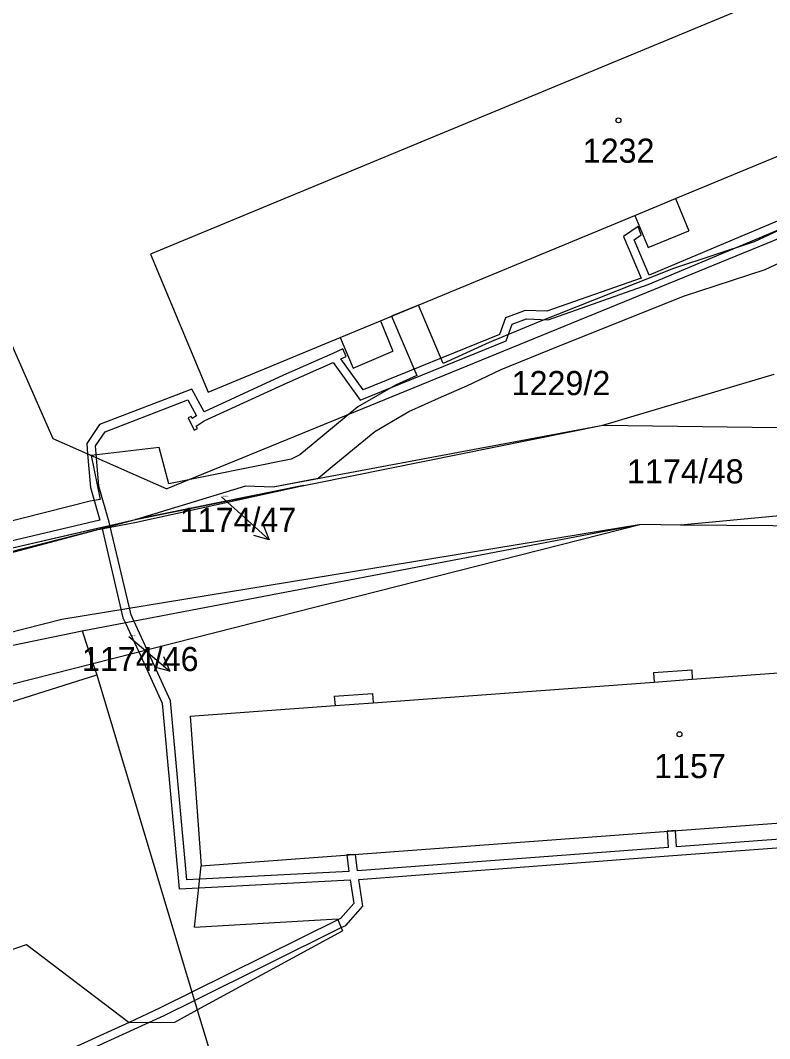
# Model space of a CAD drawing. Extents: x -785744 to -782822, y -1067550 to -1063910.
# Drawn here: x -783975.3 to -783922.5, y -1065747.4 to -1065675.6 of the extents above; entities that cross this region are included whole.
import ezdxf

# ---------------------------------------------------------------- set-up
doc = ezdxf.new("R2010")
doc.units = 0
for name, color, linetype in [('Hranice parcel', 7, 'Continuous'), ('Parcelní čísla', 7, 'Continuous'), ('Pop_ČP_popisy', 7, 'Continuous'), ('Vnitřní kresba', 7, 'Continuous'), ('Věcná břemena k části', 7, 'Continuous'), ('Značky budov', 7, 'Continuous')]:
    doc.layers.add(name, color=color, linetype=linetype)

msp = doc.modelspace()

# ---------------------------------------------------------------- linework, layer by layer
at = {"layer": 'Hranice parcel'}
for points in [[(-783903.08, -1065665.97), (-783966.1, -1065692.11)], [(-783986.93, -1065673.43), (-783973, -1065705.09)], [(-783888.41, -1065677.33), (-783964.95, -1065708.64)], [(-783929.13, -1065688.2), (-783911.14, -1065680.75)], [(-783929.13, -1065688.2), (-783928.19, -1065690.46)], [(-783949.91, -1065696.8), (-783931.98, -1065689.38)], [(-783931.98, -1065689.38), (-783931.04, -1065691.64)], [(-783931.04, -1065691.64), (-783928.19, -1065690.46)], [(-783966.1, -1065692.11), (-783962.05, -1065701.83)], [(-783949.91, -1065696.8), (-783949.03, -1065698.94)], [(-783962.05, -1065701.83), (-783952.74, -1065697.97)], [(-783952.74, -1065697.97), (-783951.84, -1065700.13)], [(-783951.84, -1065700.13), (-783949.03, -1065698.94)], [(-783934.24, -1065704.15), (-783922.17, -1065700.57)], [(-783967.17, -1065710.8), (-783934.24, -1065704.15)], [(-783957.46, -1065708.49), (-783934.24, -1065704.15)], [(-783934.24, -1065704.15), (-783909.69, -1065704.48)], [(-783973, -1065705.09), (-783964.95, -1065708.64)], [(-783967.17, -1065710.8), (-783959.39, -1065708.42)], [(-783959.39, -1065708.42), (-783957.46, -1065708.49)], [(-783977.59, -1065713.2), (-783967.17, -1065710.8)], [(-783970.93, -1065718.64), (-783931.54, -1065711.14)], [(-783970.17, -1065720.94), (-783931.54, -1065711.14)], [(-783931.54, -1065711.14), (-783928.76, -1065711.18)], [(-783928.76, -1065711.18), (-783883.16, -1065711.5)], [(-783995.82, -1065723.78), (-783970.93, -1065718.64)], [(-783970.93, -1065718.64), (-783970.17, -1065720.94)], [(-784001.35, -1065728.85), (-783970.17, -1065720.94)], [(-783970.17, -1065720.94), (-783969.9, -1065721.74)], [(-783927.94, -1065722.05), (-783908.15, -1065720.6)], [(-784001.77, -1065731.82), (-783969.9, -1065721.74)], [(-783969.9, -1065721.74), (-783962.82, -1065745.35)], [(-783930.68, -1065721.59), (-783927.98, -1065721.4)], [(-783930.68, -1065721.59), (-783930.63, -1065722.25)], [(-783927.98, -1065721.4), (-783927.94, -1065722.05)], [(-783950.42, -1065723.71), (-783930.63, -1065722.25)], [(-783953.16, -1065723.25), (-783950.46, -1065723.06)], [(-783953.16, -1065723.25), (-783953.11, -1065723.91)], [(-783950.46, -1065723.06), (-783950.42, -1065723.71)], [(-783963.31, -1065724.66), (-783953.11, -1065723.91)], [(-783963.31, -1065724.66), (-783962.53, -1065735.19)], [(-783962.53, -1065735.19), (-783894.47, -1065730.15)], [(-783963.02, -1065739.52), (-783962.53, -1065735.19)], [(-783963.02, -1065739.52), (-783952.94, -1065738.92)], [(-783952.94, -1065738.92), (-783952.59, -1065739.77)], [(-783962.82, -1065745.35), (-783952.59, -1065739.77)], [(-783978.71, -1065742.05), (-783974.84, -1065740.73)], [(-783974.84, -1065740.73), (-783967.61, -1065746.23)], [(-783964.39, -1065746.21), (-783962.82, -1065745.35)], [(-783962.82, -1065745.35), (-783961.87, -1065748.51)], [(-783967.61, -1065746.23), (-783964.39, -1065746.21)]]:
    msp.add_lwpolyline(points, dxfattribs=at)
at = {"layer": 'Pop_ČP_popisy'}
for p, q in [((-783959.99, -1065710.22), (-783957.762, -1065712.229)), ((-783967.04, -1065719.54), (-783964.748, -1065721.475))]:
    msp.add_line(p, q, dxfattribs=at)
for points in [[(-783961.11, -1065709.21), (-783959.99, -1065710.22)], [(-783958.17, -1065711.188), (-783957.762, -1065712.229), (-783958.839, -1065711.931)], [(-783967.64, -1065719.04), (-783967.04, -1065719.54)], [(-783965.189, -1065720.448), (-783964.748, -1065721.475), (-783965.834, -1065721.212)]]:
    msp.add_lwpolyline(points, dxfattribs=at)
at = {"layer": 'Vnitřní kresba'}
for points in [[(-783931.98, -1065689.38), (-783929.13, -1065688.2)], [(-783952.74, -1065697.97), (-783949.91, -1065696.8)], [(-783928.76, -1065711.18), (-783904.83, -1065708.92)], [(-784011.15, -1065722.52), (-783967.17, -1065710.8)], [(-783972.36, -1065717.81), (-783931.54, -1065711.14)], [(-783995.82, -1065723.78), (-783972.36, -1065717.81)], [(-783930.63, -1065722.25), (-783927.94, -1065722.05)], [(-783953.11, -1065723.91), (-783950.42, -1065723.71)]]:
    msp.add_lwpolyline(points, dxfattribs=at)
at = {"layer": 'Věcná břemena k části'}
for points in [[(-783921.22, -1065689.48), (-783930.98, -1065693.58)], [(-783931.76, -1065690.16), (-783932.78, -1065690.87)], [(-783931.54, -1065690.74), (-783931.76, -1065690.16)], [(-783931.04, -1065694.25), (-783920.8, -1065689.96)], [(-783920.54, -1065689.83), (-783923.58, -1065691.24)], [(-783932.78, -1065690.87), (-783931.54, -1065693.79)], [(-783932.04, -1065691.09), (-783931.54, -1065690.74)], [(-783930.98, -1065693.58), (-783932.04, -1065691.09)], [(-783923.58, -1065691.24), (-783929.26, -1065693.11)], [(-783922.81, -1065693.19), (-783919.73, -1065691.76)], [(-783929.26, -1065693.11), (-783938.79, -1065696.91)], [(-783928.55, -1065695.08), (-783922.81, -1065693.19)], [(-783931.54, -1065693.79), (-783938.19, -1065696.13)], [(-783938.09, -1065696.73), (-783931.04, -1065694.25)], [(-783938, -1065698.84), (-783928.55, -1065695.08)], [(-783947.24, -1065695.7), (-783949.13, -1065696.48)], [(-783945.48, -1065699.82), (-783947.24, -1065695.7)], [(-783939.71, -1065696.07), (-783941.09, -1065696.59)], [(-783938.19, -1065696.13), (-783939.71, -1065696.07)], [(-783949.13, -1065696.48), (-783947.35, -1065700.65)], [(-783938.79, -1065696.91), (-783942.25, -1065698.33)], [(-783941.09, -1065696.59), (-783941.53, -1065697.76)], [(-783940.63, -1065697.05), (-783939.61, -1065696.67)], [(-783939.61, -1065696.67), (-783938.09, -1065696.73)], [(-783941.05, -1065698.22), (-783940.63, -1065697.05)], [(-783951.35, -1065702.4), (-783941.05, -1065698.22)], [(-783941.53, -1065697.76), (-783951.13, -1065701.66)], [(-783942.25, -1065698.33), (-783945.48, -1065699.82)], [(-783952.55, -1065698.77), (-783953.27, -1065699.1)], [(-783952.33, -1065699.33), (-783952.55, -1065698.77)], [(-783941.4, -1065700.24), (-783938, -1065698.84)], [(-783953.27, -1065699.1), (-783956.73, -1065700.63)], [(-783956.49, -1065701.17), (-783953.25, -1065699.74)], [(-783953.25, -1065699.74), (-783951.35, -1065702.4)], [(-783952.69, -1065699.49), (-783952.33, -1065699.33)], [(-783951.13, -1065701.66), (-783952.69, -1065699.49)], [(-783943.82, -1065701.38), (-783941.4, -1065700.24)], [(-783956.73, -1065700.63), (-783962.34, -1065703.21)], [(-783962.32, -1065703.86), (-783956.49, -1065701.17)], [(-783947.35, -1065700.65), (-783948.86, -1065701.34)], [(-783963.21, -1065701.62), (-783969.71, -1065704.12)], [(-783962.34, -1065703.21), (-783963.21, -1065701.62)], [(-783948.86, -1065701.34), (-783951.5, -1065702.86)], [(-783945.6, -1065702.16), (-783943.82, -1065701.38)], [(-783969.31, -1065704.62), (-783963.49, -1065702.36)], [(-783963.49, -1065702.36), (-783962.87, -1065703.5)], [(-783947.9, -1065703.2), (-783945.6, -1065702.16)], [(-783951.5, -1065702.86), (-783954.64, -1065705.46)], [(-783950.31, -1065704.59), (-783947.9, -1065703.2)], [(-783963.24, -1065703.54), (-783963.46, -1065703.65)], [(-783963.46, -1065703.65), (-783963.03, -1065704.5)], [(-783963.17, -1065703.68), (-783963.24, -1065703.54)], [(-783962.87, -1065703.5), (-783963.17, -1065703.68)], [(-783962.9, -1065704.22), (-783962.32, -1065703.86)], [(-783969.71, -1065704.12), (-783970.6, -1065705.45)], [(-783969.98, -1065705.61), (-783969.31, -1065704.62)], [(-783963.03, -1065704.5), (-783962.81, -1065704.39)], [(-783962.81, -1065704.39), (-783962.9, -1065704.22)], [(-783953.31, -1065707.07), (-783950.31, -1065704.59)], [(-783970.6, -1065705.45), (-783970.54, -1065706.18)], [(-783954.64, -1065705.46), (-783955.58, -1065706.24)], [(-783970.54, -1065706.18), (-783970.34, -1065708.55)], [(-783965.5, -1065705.73), (-783970.28, -1065706.29)], [(-783969.91, -1065706.45), (-783969.98, -1065705.61)], [(-783964.82, -1065708.28), (-783965.5, -1065705.73)], [(-783970.28, -1065706.29), (-783969.66, -1065709.38)], [(-783969.74, -1065708.45), (-783969.91, -1065706.45)], [(-783956.19, -1065706.54), (-783964.82, -1065708.28)], [(-783955.58, -1065706.24), (-783956.19, -1065706.54)], [(-783954.3, -1065707.9), (-783953.31, -1065707.07)], [(-783957.46, -1065708.49), (-783954.3, -1065707.9)], [(-783970.34, -1065708.55), (-783969.68, -1065710.85)], [(-783969.02, -1065710.99), (-783969.74, -1065708.45)], [(-783967.22, -1065711.02), (-783955.32, -1065708.41)], [(-783955.32, -1065708.41), (-783967.17, -1065710.8)], [(-783967.17, -1065710.8), (-783959.39, -1065708.42)], [(-783959.39, -1065708.42), (-783957.46, -1065708.49)], [(-783970.37, -1065709.51), (-783978.25, -1065711.51)], [(-783969.66, -1065709.38), (-783970.37, -1065709.51)], [(-783969.68, -1065710.85), (-783977.76, -1065712.76)], [(-783969.95, -1065711.53), (-783967.22, -1065711.02)], [(-783968.97, -1065711.21), (-783969.02, -1065710.99)], [(-783967.47, -1065717.52), (-783968.97, -1065711.21)], [(-783978.63, -1065713.73), (-783969.95, -1065711.53)], [(-783977.59, -1065713.2), (-783969.55, -1065711.35)], [(-783969.55, -1065711.35), (-783968.05, -1065717.72)], [(-783967.28, -1065717.95), (-783967.47, -1065717.52)], [(-783968.05, -1065717.72), (-783967.89, -1065718.06)], [(-783967.89, -1065718.06), (-783966.94, -1065720.12)], [(-783966.35, -1065719.97), (-783967.28, -1065717.95)], [(-783966.94, -1065720.12), (-783965.29, -1065723.73)], [(-783964.71, -1065723.57), (-783966.35, -1065719.97)], [(-783965.29, -1065723.73), (-783964.1, -1065736.81)], [(-783963.56, -1065736.19), (-783964.71, -1065723.57)], [(-783929.12, -1065732.72), (-783929.72, -1065732.76)], [(-783929.72, -1065732.76), (-783929.65, -1065733.9)], [(-783929.31, -1065734.48), (-783905.47, -1065732.72)], [(-783929.05, -1065733.86), (-783929.12, -1065732.72)], [(-783905.83, -1065732.14), (-783929.05, -1065733.86)], [(-783929.65, -1065733.9), (-783951.53, -1065735.56)], [(-783951.67, -1065734.39), (-783952.27, -1065734.43)], [(-783952.27, -1065734.43), (-783952.13, -1065735.6)], [(-783951.53, -1065735.56), (-783951.67, -1065734.39)], [(-783951.44, -1065736.15), (-783929.31, -1065734.48)], [(-783952.13, -1065735.6), (-783962.64, -1065736.14)], [(-783962.64, -1065736.14), (-783963.56, -1065736.19)], [(-783962.71, -1065736.74), (-783952.04, -1065736.19)], [(-783952.04, -1065736.19), (-783951.78, -1065737.86)], [(-783951.14, -1065738.04), (-783951.44, -1065736.15)], [(-783964.1, -1065736.81), (-783962.71, -1065736.74)], [(-783951.78, -1065737.86), (-783952.72, -1065738.91)], [(-783952.36, -1065739.39), (-783951.14, -1065738.04)], [(-783952.91, -1065739), (-783963.19, -1065744.1)], [(-783952.72, -1065738.91), (-783952.91, -1065739)], [(-783963.02, -1065744.69), (-783952.68, -1065739.55)], [(-783952.68, -1065739.55), (-783952.36, -1065739.39)], [(-783963.19, -1065744.1), (-783965.42, -1065745.21)], [(-783965.16, -1065745.75), (-783963.02, -1065744.69)], [(-783965.42, -1065745.21), (-783967.61, -1065746.23)], [(-783967.61, -1065746.23), (-783977.81, -1065750.85)], [(-783977.37, -1065751.31), (-783966.19, -1065746.22)], [(-783966.19, -1065746.22), (-783965.16, -1065745.75)]]:
    msp.add_lwpolyline(points, dxfattribs=at)
at = {"layer": 'Značky budov'}
for centre in [(-783933.14, -1065682.68), (-783928.84, -1065725.93)]:
    msp.add_circle(centre, 0.175, dxfattribs=at)

# ---------------------------------------------------------------- texts
at = {"layer": 'Parcelní čísla'}
for s, height, p in [('1232', 1.7, (-783935.66, -1065685.67)), ('1229/2', 1.7, (-783940.67, -1065702.04)), ('1174/48', 1.7, (-783932.54, -1065708.26)), ('1174/47', 0.1, (-783961.11, -1065709.21)), ('1174/46', 0.1, (-783967.64, -1065719.04)), ('1157', 1.7, (-783930.63, -1065729.02))]:
    msp.add_text(s, height=height, dxfattribs=at).set_placement(p)
at = {"layer": 'Pop_ČP_popisy'}
for s, p in [('1174/47', (-783964.051, -1065711.67)), ('1174/46', (-783970.942, -1065721.48))]:
    msp.add_text(s, height=1.7, dxfattribs=at).set_placement(p)

doc.saveas('drawing.dxf')
